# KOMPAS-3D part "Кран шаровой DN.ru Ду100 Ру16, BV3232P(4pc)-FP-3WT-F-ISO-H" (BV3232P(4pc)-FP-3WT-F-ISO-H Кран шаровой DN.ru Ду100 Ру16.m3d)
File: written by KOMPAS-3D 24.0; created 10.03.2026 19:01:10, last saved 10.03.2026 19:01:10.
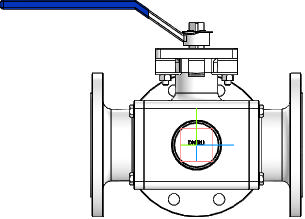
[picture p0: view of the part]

Document properties: Автор: R2D2; Полное имя файла: E:\Работа\Зайцев\BV3232P(4pc)-FP-3WT-F-ISO-H Кран шаровой DN.ru Ду15-100 Ру16\DN100\BV3232P(4pc)-FP-3WT-F-ISO-H Кран шаровой DN.ru Ду100 Ру16.m3d

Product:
- Part/product: Кран шаровой DN.ru Ду100 Ру16  | designation BV3232P(4pc)-FP-3WT-F-ISO-H
    Масса: 58.5
    Раздел спецификации: Прочие изделия
    Примечание: D160-36354

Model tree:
1. Операция без истории:1

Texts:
  BV3232P(4pc)-FP-3WT-F-ISO-H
